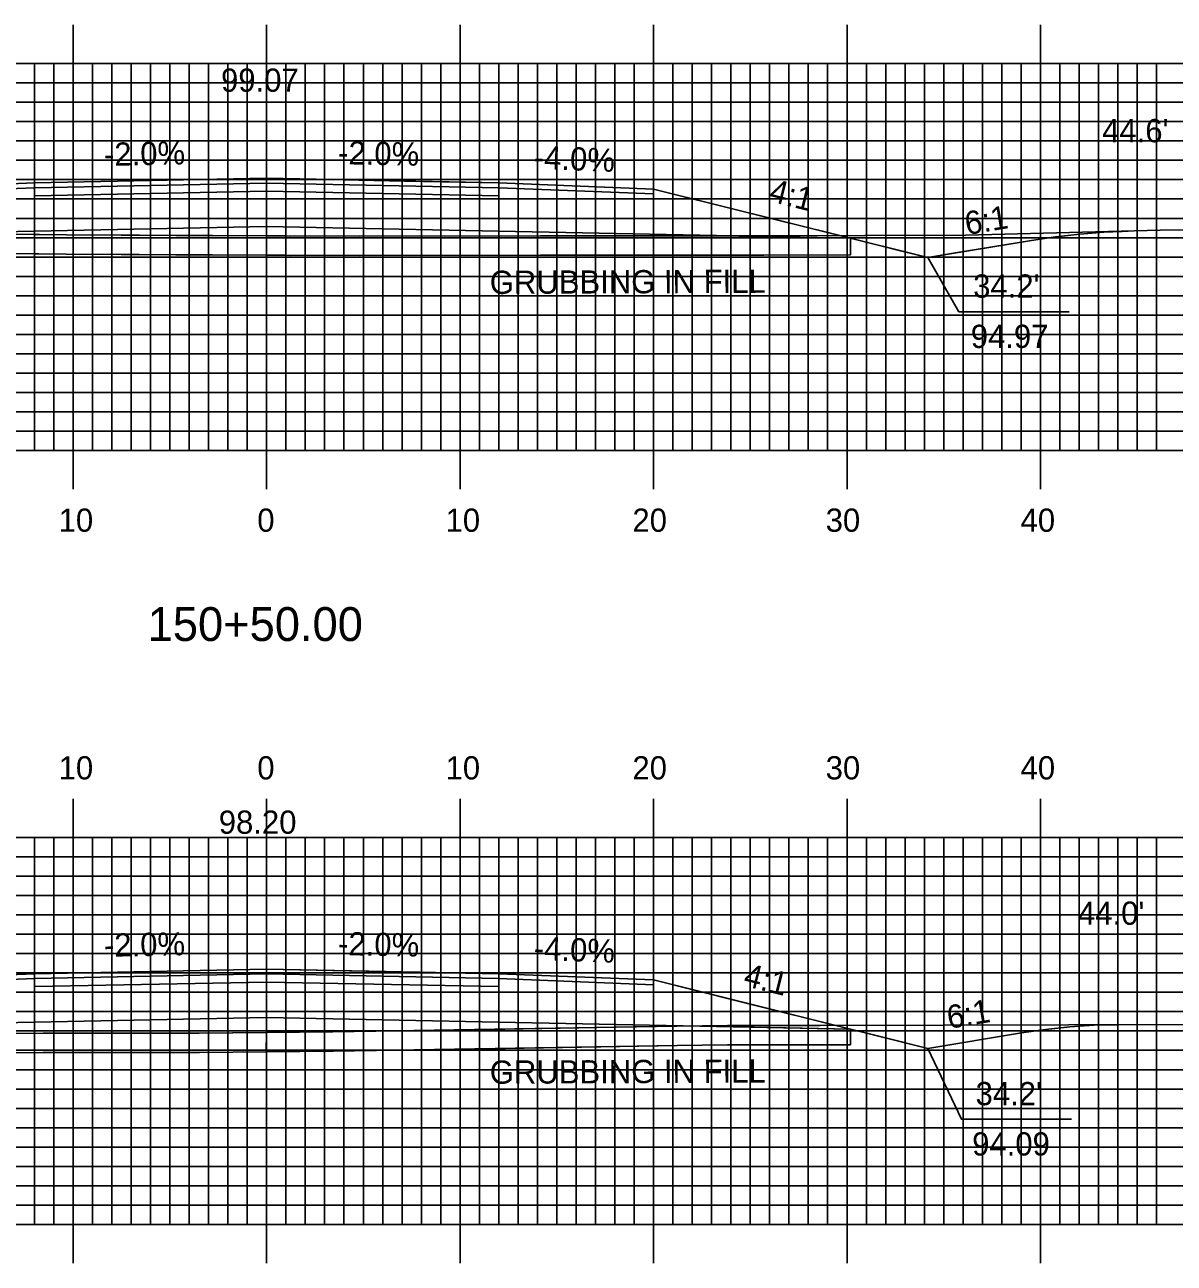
# Model space of a CAD drawing. Extents: x 1778319 to 1778662, y 442591 to 442811.
# Drawn here: x 1778471.8 to 1778531.2, y 442686.7 to 442750.7 of the extents above; entities that cross this region are included whole.
import ezdxf

# ---------------------------------------------------------------- set-up
doc = ezdxf.new("R2010")
doc.units = 0
for name, color, linetype in [('ANNOTATION', 7, 'Continuous'), ('D_Roadway_Centerline', 7, 'Continuous'), ('D_Roadway_Centerline_Text', 7, 'Continuous'), ('D_Roadway_Edge_Shoulder', 7, 'Continuous'), ('D_Roadway_Edge_TW', 7, 'Continuous'), ('D_Roadway_Pavement', 7, 'Continuous'), ('D_Roadway_SlopeLines', 7, 'Continuous'), ('D_Roadway_SubGrade', 7, 'Continuous'), ('D_Text_Standard', 7, 'Continuous'), ('GRUBBING IN FILL', 7, 'Continuous'), ('H_V ANNOTATION', 7, 'Continuous'), ('MAJOR', 7, 'Continuous'), ('MINOR', 7, 'Continuous'), ('S_Roadway_Centerline', 7, 'Continuous')]:
    doc.layers.add(name, color=color, linetype=linetype)

msp = doc.modelspace()

# ---------------------------------------------------------------- linework, layer by layer
at = {"layer": 'ANNOTATION'}
for points in [[(1778525.781, 442735.84), (1778520.09, 442735.84), (1778518.477, 442738.634)], [(1778525.906, 442694.102), (1778520.214, 442694.102), (1778518.477, 442697.759)]]:
    msp.add_lwpolyline(points, dxfattribs=at)
at = {"layer": 'D_Roadway_Centerline'}
for points in [[(1778464.723, 442742.194), (1778472.303, 442742.497), (1778472.305, 442742.497), (1778484.303, 442742.737), (1778491.445, 442742.594), (1778496.303, 442742.497), (1778504.303, 442742.177), (1778514.477, 442739.634), (1778517.132, 442738.97), (1778518.477, 442738.634), (1778519.812, 442738.857), (1778523.831, 442739.526), (1778525.081, 442739.712), (1778525.426, 442739.751), (1778526.331, 442739.854), (1778526.941, 442739.902), (1778527.581, 442739.952), (1778528.531, 442739.992), (1778528.831, 442740.004)], [(1778464.303, 442701.302), (1778472.303, 442701.622), (1778484.301, 442701.862), (1778484.303, 442701.862), (1778492.228, 442701.704), (1778496.303, 442701.622), (1778504.303, 442701.302), (1778508.741, 442700.193), (1778514.477, 442698.759), (1778516.079, 442698.359), (1778518.477, 442697.759), (1778523.319, 442698.566), (1778523.813, 442698.639), (1778524.569, 442698.749), (1778525.69, 442698.867), (1778525.819, 442698.88), (1778527.069, 442698.96), (1778527.998, 442698.981), (1778528.319, 442698.988)]]:
    msp.add_lwpolyline(points, dxfattribs=at)
at = {"layer": 'D_Roadway_Edge_Shoulder'}
for points in [[(1778472.303, 442742.497), (1778464.303, 442742.177), (1778464.303, 442741.927), (1778472.303, 442742.247)], [(1778496.303, 442742.497), (1778504.303, 442742.177), (1778504.303, 442741.927), (1778496.303, 442742.247)], [(1778472.303, 442701.622), (1778464.303, 442701.302), (1778464.303, 442701.052), (1778472.303, 442701.372)], [(1778496.303, 442701.622), (1778504.303, 442701.302), (1778504.303, 442701.052), (1778496.303, 442701.372)]]:
    msp.add_lwpolyline(points, close=True, dxfattribs=at)
at = {"layer": 'D_Roadway_Edge_TW'}
for points in [[(1778472.303, 442742.247), (1778472.303, 442742.497), (1778484.303, 442742.737), (1778496.303, 442742.497), (1778496.303, 442742.247), (1778484.303, 442742.487)], [(1778472.303, 442701.372), (1778472.303, 442701.622), (1778484.303, 442701.862), (1778496.303, 442701.622), (1778496.303, 442701.372), (1778484.303, 442701.612)]]:
    msp.add_lwpolyline(points, close=True, dxfattribs=at)
at = {"layer": 'D_Roadway_Pavement'}
for points in [[(1778472.303, 442741.831), (1778472.303, 442742.247), (1778484.303, 442742.487), (1778496.303, 442742.247), (1778496.303, 442741.831), (1778484.303, 442742.071)], [(1778472.303, 442700.956), (1778472.303, 442701.372), (1778484.303, 442701.612), (1778496.303, 442701.372), (1778496.303, 442700.956), (1778484.303, 442701.196)]]:
    msp.add_lwpolyline(points, close=True, dxfattribs=at)
at = {"layer": 'D_Roadway_SlopeLines'}
for points in [[(1778504.303, 442742.177), (1778518.477, 442738.634)], [(1778518.477, 442738.634), (1778523.831, 442739.526), (1778525.081, 442739.712), (1778526.331, 442739.854), (1778527.581, 442739.952), (1778528.831, 442740.004)], [(1778504.303, 442701.302), (1778518.477, 442697.759)], [(1778518.477, 442697.759), (1778523.318, 442698.566), (1778524.569, 442698.749), (1778525.819, 442698.88), (1778527.069, 442698.96), (1778528.319, 442698.988)]]:
    msp.add_lwpolyline(points, dxfattribs=at)
at = {"layer": 'D_Roadway_SubGrade'}
for points in [[(1778472.303, 442739.997), (1778454.129, 442739.634), (1778464.303, 442742.177), (1778464.303, 442741.927), (1778472.303, 442742.247), (1778484.303, 442742.487), (1778496.303, 442742.247), (1778504.303, 442741.927), (1778504.303, 442742.177), (1778514.476, 442739.634), (1778496.303, 442739.997), (1778484.303, 442740.237)], [(1778472.303, 442699.122), (1778454.13, 442698.759), (1778464.303, 442701.302), (1778464.303, 442701.052), (1778472.303, 442701.372), (1778484.303, 442701.612), (1778496.303, 442701.372), (1778504.303, 442701.052), (1778504.303, 442701.302), (1778514.477, 442698.759), (1778496.303, 442699.122), (1778484.303, 442699.362)]]:
    msp.add_lwpolyline(points, close=True, dxfattribs=at)
at = {"layer": 'GRUBBING IN FILL'}
for p, q in [((1778514.476, 442739.634), (1778514.476, 442738.775)), ((1778514.476, 442739.634), (1778514.476, 442738.775)), ((1778514.477, 442698.759), (1778514.477, 442697.957)), ((1778514.477, 442698.759), (1778514.477, 442697.957))]:
    msp.add_line(p, q, dxfattribs=at)
for points in [[(1778454.129, 442739.634), (1778463.216, 442739.816), (1778466.971, 442739.891), (1778473.953, 442739.813), (1778479.619, 442739.785), (1778484.303, 442739.762), (1778484.303, 442738.762), (1778479.609, 442738.785), (1778473.945, 442738.813), (1778468.311, 442738.876), (1778462.676, 442738.938), (1778458.316, 442738.917), (1778454.129, 442738.902)], [(1778454.129, 442739.634), (1778463.216, 442739.816), (1778466.971, 442739.891), (1778473.953, 442739.813), (1778479.619, 442739.785), (1778484.303, 442739.762), (1778484.303, 442738.762), (1778479.609, 442738.785), (1778473.945, 442738.813), (1778468.311, 442738.876), (1778462.676, 442738.938), (1778458.316, 442738.917), (1778454.129, 442738.902)], [(1778484.303, 442739.762), (1778489.108, 442739.751), (1778498.454, 442739.759), (1778507.764, 442739.768), (1778514.476, 442739.634), (1778514.476, 442738.775), (1778510.003, 442738.758), (1778507.798, 442738.768), (1778498.453, 442738.759), (1778489.107, 442738.751), (1778484.303, 442738.762)], [(1778484.303, 442739.762), (1778489.108, 442739.751), (1778498.454, 442739.759), (1778507.764, 442739.768), (1778514.476, 442739.634), (1778514.476, 442738.775), (1778510.003, 442738.758), (1778507.798, 442738.768), (1778498.453, 442738.759), (1778489.107, 442738.751), (1778484.303, 442738.762)], [(1778454.13, 442697.587), (1778454.13, 442698.587), (1778457.766, 442698.568), (1778461.228, 442698.551), (1778464.69, 442698.535), (1778472.756, 442698.546), (1778480.822, 442698.556), (1778484.303, 442698.587), (1778484.282, 442697.586), (1778480.827, 442697.556), (1778472.758, 442697.546), (1778464.689, 442697.535), (1778461.225, 442697.551)], [(1778454.13, 442697.587), (1778454.13, 442698.587), (1778457.766, 442698.568), (1778461.228, 442698.551), (1778464.69, 442698.535), (1778472.756, 442698.546), (1778480.822, 442698.556), (1778484.303, 442698.587), (1778484.282, 442697.586), (1778480.827, 442697.556), (1778472.758, 442697.546), (1778464.689, 442697.535), (1778461.225, 442697.551)], [(1778484.303, 442698.587), (1778487.724, 442698.617), (1778496.612, 442698.766), (1778506.179, 442698.925), (1778514.477, 442698.759), (1778514.477, 442697.957), (1778510.524, 442697.952), (1778506.821, 442697.933), (1778505.516, 442697.916), (1778496.626, 442697.766), (1778487.737, 442697.617), (1778484.282, 442697.586)], [(1778484.303, 442698.587), (1778487.724, 442698.617), (1778496.612, 442698.766), (1778506.179, 442698.925), (1778514.477, 442698.759), (1778514.477, 442697.957), (1778510.524, 442697.952), (1778506.821, 442697.933), (1778505.516, 442697.916), (1778496.626, 442697.766), (1778487.737, 442697.617), (1778484.282, 442697.586)]]:
    msp.add_lwpolyline(points, close=True, dxfattribs=at)
for points in [[(1778454.129, 442738.902), (1778462.503, 442738.932), (1778462.676, 442738.938), (1778473.945, 442738.813), (1778485.273, 442738.757), (1778485.52, 442738.752), (1778485.762, 442738.757), (1778489.107, 442738.751), (1778507.798, 442738.768), (1778510.003, 442738.758), (1778514.476, 442738.775)], [(1778454.129, 442738.902), (1778462.503, 442738.932), (1778462.676, 442738.938), (1778473.945, 442738.813), (1778485.273, 442738.757), (1778485.52, 442738.752), (1778485.762, 442738.757), (1778489.107, 442738.751), (1778507.798, 442738.768), (1778510.003, 442738.758), (1778514.476, 442738.775)], [(1778454.13, 442697.587), (1778457.761, 442697.568), (1778464.689, 442697.535), (1778480.827, 442697.556), (1778487.737, 442697.617), (1778505.516, 442697.916), (1778508.127, 442697.951), (1778512.922, 442697.953), (1778514.477, 442697.957)], [(1778454.13, 442697.587), (1778457.761, 442697.568), (1778464.689, 442697.535), (1778480.827, 442697.556), (1778487.737, 442697.617), (1778505.516, 442697.916), (1778508.127, 442697.951), (1778512.922, 442697.953), (1778514.477, 442697.957)]]:
    msp.add_lwpolyline(points, dxfattribs=at)
at = {"layer": 'MAJOR'}
for p, q in [((1778474.303, 442750.669), (1778474.303, 442748.665)), ((1778484.303, 442750.669), (1778484.303, 442748.665)), ((1778494.303, 442750.669), (1778494.303, 442748.665)), ((1778504.303, 442750.669), (1778504.303, 442748.665)), ((1778514.303, 442750.669), (1778514.303, 442748.665)), ((1778524.303, 442750.669), (1778524.303, 442748.665)), ((1778344.303, 442748.665), (1778624.303, 442748.665)), ((1778344.303, 442748.665), (1778624.303, 442748.665)), ((1778474.303, 442728.665), (1778474.303, 442748.665)), ((1778484.303, 442728.665), (1778484.303, 442748.665)), ((1778494.303, 442728.665), (1778494.303, 442748.665)), ((1778504.303, 442728.665), (1778504.303, 442748.665)), ((1778514.303, 442728.665), (1778514.303, 442748.665)), ((1778524.303, 442728.665), (1778524.303, 442748.665)), ((1778344.303, 442743.665), (1778624.303, 442743.665)), ((1778344.303, 442738.665), (1778624.303, 442738.665)), ((1778344.303, 442733.665), (1778624.303, 442733.665)), ((1778344.303, 442728.665), (1778624.303, 442728.665)), ((1778344.303, 442728.665), (1778624.303, 442728.665)), ((1778474.303, 442726.661), (1778474.303, 442728.665)), ((1778484.303, 442726.661), (1778484.303, 442728.665)), ((1778494.303, 442726.661), (1778494.303, 442728.665)), ((1778504.303, 442726.661), (1778504.303, 442728.665)), ((1778514.303, 442726.661), (1778514.303, 442728.665)), ((1778524.303, 442726.661), (1778524.303, 442728.665)), ((1778474.303, 442710.669), (1778474.303, 442708.665)), ((1778484.303, 442710.669), (1778484.303, 442708.665)), ((1778494.303, 442710.669), (1778494.303, 442708.665)), ((1778504.303, 442710.669), (1778504.303, 442708.665)), ((1778514.303, 442710.669), (1778514.303, 442708.665)), ((1778524.303, 442710.669), (1778524.303, 442708.665)), ((1778344.303, 442708.665), (1778624.303, 442708.665)), ((1778344.303, 442708.665), (1778624.303, 442708.665)), ((1778474.303, 442688.665), (1778474.303, 442708.665)), ((1778484.303, 442688.665), (1778484.303, 442708.665)), ((1778494.303, 442688.665), (1778494.303, 442708.665)), ((1778504.303, 442688.665), (1778504.303, 442708.665)), ((1778514.303, 442688.665), (1778514.303, 442708.665)), ((1778524.303, 442688.665), (1778524.303, 442708.665)), ((1778344.303, 442703.665), (1778624.303, 442703.665)), ((1778344.303, 442698.665), (1778624.303, 442698.665)), ((1778344.303, 442693.665), (1778624.303, 442693.665)), ((1778344.303, 442688.665), (1778624.303, 442688.665)), ((1778344.303, 442688.665), (1778624.303, 442688.665)), ((1778474.303, 442686.661), (1778474.303, 442688.665)), ((1778484.303, 442686.661), (1778484.303, 442688.665)), ((1778494.303, 442686.661), (1778494.303, 442688.665)), ((1778504.303, 442686.661), (1778504.303, 442688.665)), ((1778514.303, 442686.661), (1778514.303, 442688.665)), ((1778524.303, 442686.661), (1778524.303, 442688.665))]:
    msp.add_line(p, q, dxfattribs=at)
at = {"layer": 'MINOR'}
for p, q in [((1778472.303, 442728.665), (1778472.303, 442748.665)), ((1778473.303, 442728.665), (1778473.303, 442748.665)), ((1778475.303, 442728.665), (1778475.303, 442748.665)), ((1778476.303, 442728.665), (1778476.303, 442748.665)), ((1778477.303, 442728.665), (1778477.303, 442748.665)), ((1778478.303, 442728.665), (1778478.303, 442748.665)), ((1778479.303, 442728.665), (1778479.303, 442748.665)), ((1778480.303, 442728.665), (1778480.303, 442748.665)), ((1778481.303, 442728.665), (1778481.303, 442748.665)), ((1778482.303, 442728.665), (1778482.303, 442748.665)), ((1778483.303, 442728.665), (1778483.303, 442748.665)), ((1778485.303, 442728.665), (1778485.303, 442748.665)), ((1778486.303, 442728.665), (1778486.303, 442748.665)), ((1778487.303, 442728.665), (1778487.303, 442748.665)), ((1778488.303, 442728.665), (1778488.303, 442748.665)), ((1778489.303, 442728.665), (1778489.303, 442748.665)), ((1778490.303, 442728.665), (1778490.303, 442748.665)), ((1778491.303, 442728.665), (1778491.303, 442748.665)), ((1778492.303, 442728.665), (1778492.303, 442748.665)), ((1778493.303, 442728.665), (1778493.303, 442748.665)), ((1778495.303, 442728.665), (1778495.303, 442748.665)), ((1778496.303, 442728.665), (1778496.303, 442748.665)), ((1778497.303, 442728.665), (1778497.303, 442748.665)), ((1778498.303, 442728.665), (1778498.303, 442748.665)), ((1778499.303, 442728.665), (1778499.303, 442748.665)), ((1778500.303, 442728.665), (1778500.303, 442748.665)), ((1778501.303, 442728.665), (1778501.303, 442748.665)), ((1778502.303, 442728.665), (1778502.303, 442748.665)), ((1778503.303, 442728.665), (1778503.303, 442748.665)), ((1778505.303, 442728.665), (1778505.303, 442748.665)), ((1778506.303, 442728.665), (1778506.303, 442748.665)), ((1778507.303, 442728.665), (1778507.303, 442748.665)), ((1778508.303, 442728.665), (1778508.303, 442748.665)), ((1778509.303, 442728.665), (1778509.303, 442748.665)), ((1778510.303, 442728.665), (1778510.303, 442748.665)), ((1778511.303, 442728.665), (1778511.303, 442748.665)), ((1778512.303, 442728.665), (1778512.303, 442748.665)), ((1778513.303, 442728.665), (1778513.303, 442748.665)), ((1778515.303, 442728.665), (1778515.303, 442748.665)), ((1778516.303, 442728.665), (1778516.303, 442748.665)), ((1778517.303, 442728.665), (1778517.303, 442748.665)), ((1778518.303, 442728.665), (1778518.303, 442748.665)), ((1778519.303, 442728.665), (1778519.303, 442748.665)), ((1778520.303, 442728.665), (1778520.303, 442748.665)), ((1778521.303, 442728.665), (1778521.303, 442748.665)), ((1778522.303, 442728.665), (1778522.303, 442748.665)), ((1778523.303, 442728.665), (1778523.303, 442748.665)), ((1778525.303, 442728.665), (1778525.303, 442748.665)), ((1778526.303, 442728.665), (1778526.303, 442748.665)), ((1778527.303, 442728.665), (1778527.303, 442748.665)), ((1778528.303, 442728.665), (1778528.303, 442748.665)), ((1778529.303, 442728.665), (1778529.303, 442748.665)), ((1778530.303, 442728.665), (1778530.303, 442748.665)), ((1778344.303, 442747.665), (1778624.303, 442747.665)), ((1778344.303, 442746.665), (1778624.303, 442746.665)), ((1778344.303, 442745.665), (1778624.303, 442745.665)), ((1778344.303, 442744.665), (1778624.303, 442744.665)), ((1778344.303, 442742.665), (1778624.303, 442742.665)), ((1778344.303, 442741.665), (1778624.303, 442741.665)), ((1778344.303, 442740.665), (1778624.303, 442740.665)), ((1778344.303, 442739.665), (1778624.303, 442739.665)), ((1778344.303, 442737.665), (1778624.303, 442737.665)), ((1778344.303, 442736.665), (1778624.303, 442736.665)), ((1778344.303, 442735.665), (1778624.303, 442735.665)), ((1778344.303, 442734.665), (1778624.303, 442734.665)), ((1778344.303, 442732.665), (1778624.303, 442732.665)), ((1778344.303, 442731.665), (1778624.303, 442731.665)), ((1778344.303, 442730.665), (1778624.303, 442730.665)), ((1778344.303, 442729.665), (1778624.303, 442729.665)), ((1778472.303, 442688.665), (1778472.303, 442708.665)), ((1778473.303, 442688.665), (1778473.303, 442708.665)), ((1778475.303, 442688.665), (1778475.303, 442708.665)), ((1778476.303, 442688.665), (1778476.303, 442708.665)), ((1778477.303, 442688.665), (1778477.303, 442708.665)), ((1778478.303, 442688.665), (1778478.303, 442708.665)), ((1778479.303, 442688.665), (1778479.303, 442708.665)), ((1778480.303, 442688.665), (1778480.303, 442708.665)), ((1778481.303, 442688.665), (1778481.303, 442708.665)), ((1778482.303, 442688.665), (1778482.303, 442708.665)), ((1778483.303, 442688.665), (1778483.303, 442708.665)), ((1778485.303, 442688.665), (1778485.303, 442708.665)), ((1778486.303, 442688.665), (1778486.303, 442708.665)), ((1778487.303, 442688.665), (1778487.303, 442708.665)), ((1778488.303, 442688.665), (1778488.303, 442708.665)), ((1778489.303, 442688.665), (1778489.303, 442708.665)), ((1778490.303, 442688.665), (1778490.303, 442708.665)), ((1778491.303, 442688.665), (1778491.303, 442708.665)), ((1778492.303, 442688.665), (1778492.303, 442708.665)), ((1778493.303, 442688.665), (1778493.303, 442708.665)), ((1778495.303, 442688.665), (1778495.303, 442708.665)), ((1778496.303, 442688.665), (1778496.303, 442708.665)), ((1778497.303, 442688.665), (1778497.303, 442708.665)), ((1778498.303, 442688.665), (1778498.303, 442708.665)), ((1778499.303, 442688.665), (1778499.303, 442708.665)), ((1778500.303, 442688.665), (1778500.303, 442708.665)), ((1778501.303, 442688.665), (1778501.303, 442708.665)), ((1778502.303, 442688.665), (1778502.303, 442708.665)), ((1778503.303, 442688.665), (1778503.303, 442708.665)), ((1778505.303, 442688.665), (1778505.303, 442708.665)), ((1778506.303, 442688.665), (1778506.303, 442708.665)), ((1778507.303, 442688.665), (1778507.303, 442708.665)), ((1778508.303, 442688.665), (1778508.303, 442708.665)), ((1778509.303, 442688.665), (1778509.303, 442708.665)), ((1778510.303, 442688.665), (1778510.303, 442708.665)), ((1778511.303, 442688.665), (1778511.303, 442708.665)), ((1778512.303, 442688.665), (1778512.303, 442708.665)), ((1778513.303, 442688.665), (1778513.303, 442708.665)), ((1778515.303, 442688.665), (1778515.303, 442708.665)), ((1778516.303, 442688.665), (1778516.303, 442708.665)), ((1778517.303, 442688.665), (1778517.303, 442708.665)), ((1778518.303, 442688.665), (1778518.303, 442708.665)), ((1778519.303, 442688.665), (1778519.303, 442708.665)), ((1778520.303, 442688.665), (1778520.303, 442708.665)), ((1778521.303, 442688.665), (1778521.303, 442708.665)), ((1778522.303, 442688.665), (1778522.303, 442708.665)), ((1778523.303, 442688.665), (1778523.303, 442708.665)), ((1778525.303, 442688.665), (1778525.303, 442708.665)), ((1778526.303, 442688.665), (1778526.303, 442708.665)), ((1778527.303, 442688.665), (1778527.303, 442708.665)), ((1778528.303, 442688.665), (1778528.303, 442708.665)), ((1778529.303, 442688.665), (1778529.303, 442708.665)), ((1778530.303, 442688.665), (1778530.303, 442708.665)), ((1778344.303, 442707.665), (1778624.303, 442707.665)), ((1778344.303, 442706.665), (1778624.303, 442706.665)), ((1778344.303, 442705.665), (1778624.303, 442705.665)), ((1778344.303, 442704.665), (1778624.303, 442704.665)), ((1778344.303, 442702.665), (1778624.303, 442702.665)), ((1778344.303, 442701.665), (1778624.303, 442701.665)), ((1778344.303, 442700.665), (1778624.303, 442700.665)), ((1778344.303, 442699.665), (1778624.303, 442699.665)), ((1778344.303, 442697.665), (1778624.303, 442697.665)), ((1778344.303, 442696.665), (1778624.303, 442696.665)), ((1778344.303, 442695.665), (1778624.303, 442695.665)), ((1778344.303, 442694.665), (1778624.303, 442694.665)), ((1778344.303, 442692.665), (1778624.303, 442692.665)), ((1778344.303, 442691.665), (1778624.303, 442691.665)), ((1778344.303, 442690.665), (1778624.303, 442690.665)), ((1778344.303, 442689.665), (1778624.303, 442689.665))]:
    msp.add_line(p, q, dxfattribs=at)
at = {"layer": 'S_Roadway_Centerline'}
for points in [[(1778417.84, 442739.354), (1778429.256, 442739.09), (1778440.814, 442739.846), (1778441.767, 442739.858), (1778462.483, 442739.932), (1778462.664, 442739.938), (1778473.953, 442739.813), (1778485.286, 442739.757), (1778485.518, 442739.752), (1778485.752, 442739.757), (1778489.108, 442739.751), (1778507.8, 442739.768), (1778510.003, 442739.758), (1778520.441, 442739.799), (1778530.487, 442740.045), (1778535.142, 442740.071)], [(1778344.303, 442697.541), (1778351.743, 442697.564), (1778363.809, 442697.941), (1778369.805, 442697.91), (1778375.274, 442698.29), (1778380.708, 442698.555), (1778397.812, 442698.308), (1778404.224, 442698.223), (1778411.588, 442698.3), (1778420.475, 442698.413), (1778434.487, 442699.007), (1778443.083, 442699.035), (1778449.532, 442698.611), (1778457.766, 442698.568), (1778464.69, 442698.535), (1778480.822, 442698.556), (1778487.724, 442698.617), (1778505.501, 442698.916), (1778508.12, 442698.951), (1778512.921, 442698.953), (1778532.182, 442698.997)]]:
    msp.add_lwpolyline(points, dxfattribs=at)

# ---------------------------------------------------------------- texts
at = {"layer": 'ANNOTATION'}
for s, rotation, p in [('-2.0%', 1.1457, (1778475.91, 442743.37)), ('-2.0%', 358.85424, (1778487.989, 442743.464)), ('-4.0%', 357.70947, (1778498.095, 442743.227)), ('4:1', 345.96526, (1778510.223, 442741.559)), ('6:1', 9.45837, (1778520.497, 442739.798)), ('-2.0%', 1.1457, (1778475.908, 442702.495)), ('-2.0%', 358.85424, (1778487.989, 442702.589)), ('-4.0%', 357.70947, (1778498.095, 442702.352)), ('4:1', 345.96618, (1778508.896, 442701.016)), ('6:1', 9.46331, (1778519.573, 442698.77))]:
    msp.add_text(s, height=1.2, rotation=rotation, dxfattribs=at).set_placement(p)
for s, p in [("34.2'", (1778520.824, 442736.566)), ('94.97', (1778520.701, 442733.966)), ("34.2'", (1778520.949, 442694.828)), ('94.09', (1778520.772, 442692.228))]:
    msp.add_text(s, height=1.2, dxfattribs=at).set_placement(p)
at = {"layer": 'D_Roadway_Centerline'}
for s, p in [('C', (1778484.298, 442742.737)), ('L', (1778484.303, 442742.73)), ('C', (1778484.298, 442701.862)), ('L', (1778484.303, 442701.855))]:
    msp.add_text(s, height=0.0146, dxfattribs=at).set_placement(p)
at = {"layer": 'D_Roadway_Centerline_Text'}
for s, p in [('99.07', (1778481.949, 442747.207)), ('98.20', (1778481.831, 442708.857))]:
    msp.add_text(s, height=1.2, dxfattribs=at).set_placement(p)
at = {"layer": 'D_Text_Standard'}
for s, p in [("44.6'", (1778527.491, 442744.597)), ("44.0'", (1778526.244, 442704.153))]:
    msp.add_text(s, height=1.2, dxfattribs=at).set_placement(p)
at = {"layer": 'GRUBBING IN FILL'}
for p in [(1778495.84, 442736.756), (1778495.84, 442695.935)]:
    msp.add_text('GRUBBING IN FILL', height=1.2, rotation=0.24521, dxfattribs=at).set_placement(p)
at = {"layer": 'H_V ANNOTATION'}
for s, height, p in [('10', 1.2, (1778473.554, 442724.465)), ('0', 1.2, (1778483.821, 442724.465)), ('10', 1.2, (1778493.554, 442724.465)), ('20', 1.2, (1778503.211, 442724.465)), ('30', 1.2, (1778513.2, 442724.465)), ('40', 1.2, (1778523.275, 442724.465)), ('150+50.00', 1.75, (1778478.154, 442718.821)), ('10', 1.2, (1778473.554, 442711.665)), ('0', 1.2, (1778483.821, 442711.665)), ('10', 1.2, (1778493.554, 442711.665)), ('20', 1.2, (1778503.211, 442711.665)), ('30', 1.2, (1778513.2, 442711.665)), ('40', 1.2, (1778523.275, 442711.665))]:
    msp.add_text(s, height=height, dxfattribs=at).set_placement(p)

doc.saveas('drawing.dxf')
